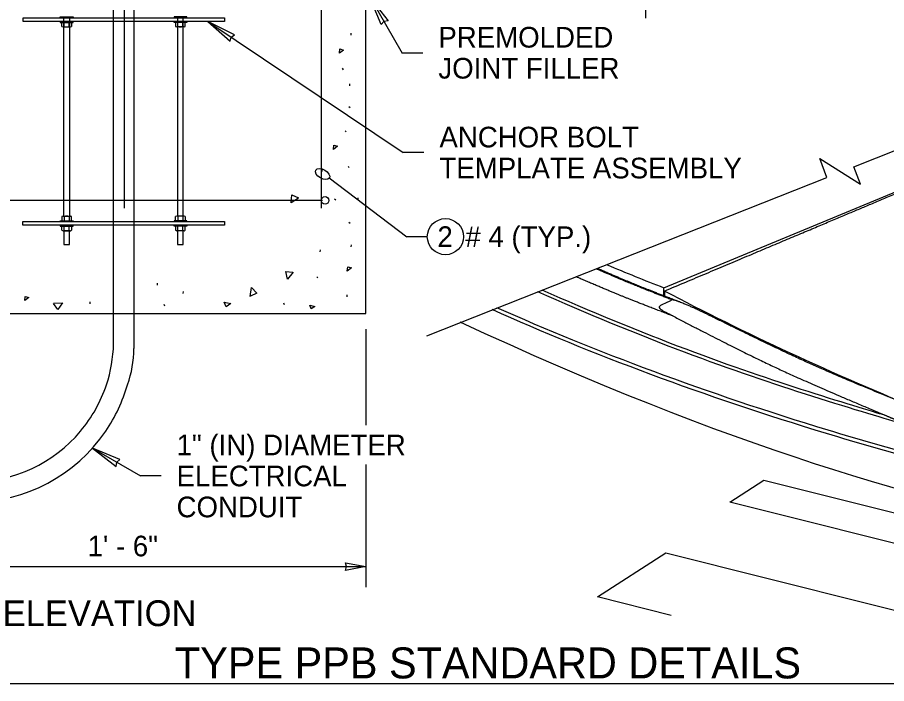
# Model space of a CAD drawing. Extents: x 99862 to 103680, y 99470 to 105076.
# Drawn here: x 101182 to 101855, y 100000 to 100515 of the extents above; entities that cross this region are included whole.
import ezdxf

# ---------------------------------------------------------------- set-up
doc = ezdxf.new("R2010")
doc.units = 0
for name, color, linetype in [('Level 1', 7, 'Continuous'), ('Level 12', 7, 'Continuous'), ('Level 13', 7, 'Continuous'), ('Level 15', 7, 'Continuous'), ('Level 16', 7, 'Continuous'), ('Level 19', 7, 'Continuous'), ('Level 20', 7, 'Continuous'), ('Level 22', 7, 'Continuous'), ('Level 24', 7, 'Continuous'), ('Level 25', 7, 'Continuous'), ('Level 37', 7, 'Continuous'), ('Level 4', 7, 'Continuous')]:
    doc.layers.add(name, color=color, linetype=linetype)

msp = doc.modelspace()

# ---------------------------------------------------------------- linework, layer by layer
at = {"layer": 'Level 1'}
msp.add_lwpolyline([(99862, 99999.5), (103151, 99999.5), (103151, 102075.5), (99862, 102075.5)], close=True, dxfattribs=at)
msp.add_lwpolyline([(101076.55, 100590.62), (101076.55, 100286.04), (101256.16, 100286.04), (101256.2, 100286.04), (101451.55, 100286.04), (101451.55, 100590.62)], dxfattribs=at)
at = {"layer": 'Level 12'}
for p, q in [((101216.1, 100508.44), (101216.1, 100511.61)), ((101217.11, 100508.12), (101222.73, 100508.12)), ((101218, 100508.44), (101218, 100511.61)), ((101221.78, 100508.47), (101221.78, 100511.65)), ((101223.68, 100511.65), (101223.68, 100508.47)), ((101304.19, 100511.65), (101304.19, 100508.47)), ((101310.76, 100508.12), (101305.14, 100508.12)), ((101306.09, 100508.47), (101306.09, 100511.65)), ((101309.88, 100508.44), (101309.88, 100511.61)), ((101311.77, 100508.44), (101311.77, 100511.61)), ((101216.1, 100361.22), (101216.1, 100358.04)), ((101217.11, 100361.54), (101222.73, 100361.54)), ((101218, 100361.22), (101218, 100358.04)), ((101221.78, 100361.18), (101221.78, 100358.01)), ((101223.68, 100358.01), (101223.68, 100361.18)), ((101304.19, 100358.01), (101304.19, 100361.18)), ((101310.76, 100361.54), (101305.14, 100361.54)), ((101306.09, 100361.18), (101306.09, 100358.01)), ((101309.88, 100361.22), (101309.88, 100358.04)), ((101311.77, 100361.22), (101311.77, 100358.04)), ((101216.1, 100350.61), (101216.1, 100353.78)), ((101218, 100350.61), (101218, 100353.78)), ((101221.78, 100350.65), (101221.78, 100353.82)), ((101223.68, 100353.82), (101223.68, 100350.65)), ((101304.19, 100353.82), (101304.19, 100350.65)), ((101306.09, 100350.65), (101306.09, 100353.82)), ((101309.88, 100350.61), (101309.88, 100353.78)), ((101311.77, 100350.61), (101311.77, 100353.78)), ((101217.11, 100350.29), (101222.73, 100350.29)), ((101310.76, 100350.29), (101305.14, 100350.29))]:
    msp.add_line(p, q, dxfattribs=at)
for points in [[(101214.96, 100515.15), (101214.96, 100515.85), (101224.82, 100515.85), (101224.82, 100515.15)], [(101312.91, 100515.15), (101312.91, 100515.85), (101303.05, 100515.85), (101303.05, 100515.15)], [(101214.96, 100512.33), (101214.96, 100511.63), (101224.82, 100511.63), (101224.82, 100512.33)], [(101312.91, 100512.33), (101312.91, 100511.63), (101303.05, 100511.63), (101303.05, 100512.33)], [(101214.96, 100357.32), (101214.96, 100358.03), (101224.82, 100358.03), (101224.82, 100357.32)], [(101214.96, 100354.51), (101214.96, 100353.8), (101224.82, 100353.8), (101224.82, 100354.51)], [(101312.91, 100357.32), (101312.91, 100358.03), (101303.05, 100358.03), (101303.05, 100357.32)], [(101312.91, 100354.51), (101312.91, 100353.8), (101303.05, 100353.8), (101303.05, 100354.51)]]:
    msp.add_lwpolyline(points, dxfattribs=at)
for centre, radius, start, end in [((101217.05, 100509.68), 1.56, 232.65869, 307.34131), ((101219.83, 100514.38), 6.22, 252.81691, 288.29858), ((101222.73, 100509.56), 1.45, 229.05783, 310.95226), ((101305.14, 100509.56), 1.45, 229.04774, 310.94217), ((101308.04, 100514.38), 6.22, 251.70142, 287.18309), ((101310.82, 100509.68), 1.56, 232.65869, 307.34131), ((101217.05, 100359.98), 1.56, 52.65869, 127.34131), ((101219.83, 100355.28), 6.22, 71.70142, 107.18309), ((101222.73, 100360.09), 1.45, 49.04774, 130.94217), ((101305.14, 100360.09), 1.45, 49.05783, 130.95226), ((101308.04, 100355.28), 6.22, 72.81691, 108.29858), ((101310.82, 100359.98), 1.56, 52.65869, 127.34131), ((101217.05, 100351.85), 1.56, 232.65869, 307.34131), ((101219.83, 100356.55), 6.22, 252.81691, 288.29858), ((101222.73, 100351.74), 1.45, 229.05783, 310.95226), ((101305.14, 100351.74), 1.45, 229.04774, 310.94217), ((101308.04, 100356.55), 6.22, 251.70142, 287.18309), ((101310.82, 100351.85), 1.56, 232.65869, 307.34131)]:
    msp.add_arc(centre, radius, start, end, dxfattribs=at)
at = {"layer": 'Level 13'}
for points in [[(101186.06, 100515.15), (101342.23, 100515.15), (101342.23, 100512.33), (101186.06, 100512.33)], [(101186.02, 100357.32), (101342.19, 100357.32), (101342.19, 100354.51), (101186.02, 100354.51)]]:
    msp.add_lwpolyline(points, close=True, dxfattribs=at)
at = {"layer": 'Level 15'}
for p, q in [((101454.82, 100531.18), (101479.84, 100487.84)), ((101329.26, 100512.33), (101480.68, 100410.79)), ((101495.84, 100487.84), (101479.84, 100487.84)), ((101496.68, 100410.79), (101480.68, 100410.79)), ((101423.36, 100391.16), (101483.29, 100345.66)), ((101499.29, 100345.66), (101483.29, 100345.66)), ((101451.55, 100274.04), (101451.55, 100199.73)), ((101239.85, 100181.78), (101277.02, 100160.31)), ((101451.55, 100169.08), (101451.55, 100074.08)), ((101293.02, 100160.31), (101277.02, 100160.31)), ((101076.55, 100090.08), (101451.55, 100090.08))]:
    msp.add_line(p, q, dxfattribs=at)
for points in [[(101668.19, 100603.82), (101668.19, 100567.96), (101675.93, 100567.96), (101660.44, 100552.48), (101668.19, 100552.48), (101668.19, 100514.95)], [(101498.79, 100268.74), (101808.82, 100391.53), (101803.31, 100406.18), (101834.95, 100386.21), (101829.73, 100399.81), (102002.67, 100468.3)]]:
    msp.add_lwpolyline(points, dxfattribs=at)
for points in [[(101454.82, 100531.18), (101468.82, 100512.91), (101465.7, 100512.33), (101463.65, 100509.92)], [(101329.26, 100512.33), (101346.55, 100497.14), (101347.34, 100500.21), (101349.88, 100502.1)], [(101239.85, 100181.78), (101258.12, 100167.78), (101258.7, 100170.89), (101261.11, 100172.95)], [(101451.55, 100090.08), (101435.83, 100086.99), (101436.56, 100090.08), (101435.83, 100093.16)]]:
    msp.add_lwpolyline(points, close=True, dxfattribs=at)
msp.add_ellipse((101418.17, 100394.16), major_axis=(-5.2, 3), ratio=0.57735, dxfattribs=at)
at = {"layer": 'Level 16'}
for p, q in [((101256.2, 100286.04), (101256.2, 100686.74)), ((101271.83, 100686.74), (101271.83, 100286.04)), ((101256.2, 100262.67), (101256.2, 100286.04)), ((101271.83, 100286.04), (101271.83, 100258.98))]:
    msp.add_line(p, q, dxfattribs=at)
for centre, radius, start, end in [((101146.86, 100265.28), 109.38, 341.74861, 358.63542), ((101194.5, 100257.9), 77.33, 339.66254, 0.80445), ((101144.5, 100266.66), 112.05, 320.21568, 341.45254), ((101145.84, 100265.64), 126.02, 325.88535, 344.05402), ((101146.83, 100265.28), 109.38, 270, 319.9948), ((101146.83, 100265.28), 125, 270, 325.77113)]:
    msp.add_arc(centre, radius, start, end, dxfattribs=at)
at = {"layer": 'Level 19'}
for p, q in [((101440.17, 100501.61), (101440.28, 100503.19)), ((101433.37, 100476.06), (101434.02, 100474.76)), ((101439.19, 100462.41), (101439.3, 100463.99)), ((101438.58, 100446.41), (101439.51, 100445.73)), ((101435.57, 100427.72), (101436.5, 100427.04)), ((101437.9, 100400.03), (101438.83, 100399.34)), ((101417.75, 100396.26), (101417.86, 100397.84)), ((101427.49, 100374.93), (101428.42, 100374.25)), ((101445.71, 100374.24), (101445.82, 100375.82)), ((101438.48, 100356.84), (101439.41, 100356.16)), ((101440.4, 100337.77), (101440.51, 100339.34)), ((101416.36, 100333.92), (101416.47, 100335.5)), ((101413.57, 100314.47), (101414.5, 100313.78)), ((101290.13, 100308.15), (101290.24, 100309.73)), ((101310.18, 100301.58), (101310.29, 100303.15)), ((101437.17, 100298.95), (101437.28, 100300.53)), ((101238.03, 100293.67), (101238.13, 100295.24)), ((101295.13, 100293.46), (101295.77, 100292.16)), ((101387.75, 100294.38), (101388.4, 100293.08))]:
    msp.add_line(p, q, dxfattribs=at)
for points in [[(101431.23, 100487.78), (101431.56, 100491.09), (101434.43, 100490.22), (101431.23, 100487.78)], [(101426.51, 100413.28), (101426.83, 100416.59), (101429.71, 100415.72), (101426.51, 100413.28)], [(101399.56, 100375.57), (101393.69, 100371.89), (101394.33, 100378.04), (101399.46, 100375.63)], [(101395.33, 100318.09), (101391.07, 100312.63), (101389.57, 100318.62), (101395.21, 100318.11)], [(101437.26, 100318.98), (101437.58, 100322.29), (101440.45, 100321.42), (101437.26, 100318.98)], [(101362.08, 100299.41), (101363.03, 100306.27), (101367.33, 100301.83), (101362.19, 100299.45)], [(101187.36, 100296.1), (101187.68, 100299.41), (101190.56, 100298.54), (101187.36, 100296.1)], [(101209.65, 100294.1), (101216.57, 100294.35), (101212.94, 100289.35), (101209.71, 100293.99)], [(101347.06, 100293.79), (101343.4, 100291.29), (101341.83, 100294.97), (101347.06, 100293.79)], [(101412.11, 100291.6), (101409.36, 100289.72), (101408.18, 100292.48), (101412.11, 100291.6)]]:
    msp.add_lwpolyline(points, dxfattribs=at)
at = {"layer": 'Level 20'}
msp.add_circle((101513.29, 100345.66), 14, dxfattribs=at)
at = {"layer": 'Level 22'}
for points, degree in [([(101689.01, 100296.63), (101668.98, 100304.43), (101649.42, 100312.42), (101630.35, 100320.6)], 2), ([(101694.6, 100295.11), (101672.88, 100303.48), (101651.73, 100312.09), (101631.15, 100320.91)], 2), ([(101689.42, 100284.27), (101663.77, 100294.05), (101638.86, 100304.14), (101614.71, 100314.52)], 2), ([(101868.07, 100200.48), (101857.33, 100203.6), (101799.88, 100220.68), (101702.21, 100253.55), (101622.16, 100286.24), (101584.94, 100302.94)], 3), ([(101855.05, 100206.92), (101849.13, 100208.67), (101796.66, 100224.43), (101704.32, 100255.51), (101624.94, 100287.87), (101588.32, 100304.26)], 3), ([(101689.01, 100296.63), (101685.29, 100294.97), (101682.01, 100293.23), (101677.75, 100291.36), (101680.63, 100288.84), (101685.03, 100286.64), (101689.01, 100284.47), (101689.42, 100284.27)], 3), ([(101694.69, 100295.08), (101693.13, 100295.65), (101691.58, 100296.29), (101689.75, 100296.64)], 2), ([(101722.57, 100282.35), (101713.61, 100286.74), (101704.55, 100291.12), (101694.69, 100295.08)], 2), ([(102481.65, 100065.04), (102470.71, 100066.1), (102401.87, 100073.06), (102334.07, 100081.62), (102222.02, 100098.24), (102111.99, 100117.08), (101954.64, 100151.69), (101806.49, 100192.34), (101670.46, 100238.13), (101587.98, 100271.84), (101549.47, 100289.15)], 3), ([(102482.21, 100067.76), (102471.26, 100068.82), (102402.47, 100075.77), (102334.73, 100084.32), (102222.8, 100100.92), (102112.91, 100119.74), (101955.73, 100154.32), (101807.75, 100194.92), (101672.73, 100240.37), (101591.05, 100273.69), (101553.24, 100290.62)], 3), ([(102477.39, 100044.55), (102447.94, 100047.42), (102392.79, 100053.37), (102031.32, 100099.54), (101734.5, 100181.6), (101524.73, 100279.53)], 3), ([(101689.42, 100284.27), (101741.59, 100257.15), (101796.94, 100231.29), (101855.05, 100206.92)], 2), ([(101883.13, 100210.83), (101827.07, 100233.36), (101773.42, 100257.25), (101722.57, 100282.35)], 2), ([(101855.05, 100206.92), (101859.51, 100204.98), (101864.21, 100203.1), (101867.89, 100200.83)], 2)]:
    msp.add_open_spline(points, degree=degree, dxfattribs=at)
at = {"layer": 'Level 24'}
for points in [[(102099.46, 100072.14), (102073.01, 100055.09), (101733.55, 100140.13), (101760, 100157.18), (102099.46, 100072.14)], [(101688.2, 100052.35), (101631.04, 100066.67), (101683.94, 100100.78), (101920.99, 100041.39)]]:
    msp.add_lwpolyline(points, dxfattribs=at)
at = {"layer": 'Level 25'}
for p, q in [((101264.66, 100367.65), (101264.66, 100673.98)), ((101417.32, 100367.65), (101417.32, 100673.98)), ((101418.12, 100373.76), (101111.21, 100373.76))]:
    msp.add_line(p, q, dxfattribs=at)
msp.add_circle((101420.06, 100373.76), 2.92, dxfattribs=at)
at = {"layer": 'Level 37'}
for p, q in [((101682.46, 100306.12), (101987.6, 100432.32)), ((101682.59, 100299.79), (101682.46, 100306.12))]:
    msp.add_line(p, q, dxfattribs=at)
msp.add_ellipse((102913.55, 100826.46), major_axis=(1749.62, 27.04), ratio=0.40566, start_param=3.889727, end_param=3.925643, dxfattribs=at)
for points, degree in [([(101683.03, 100303.55), (101784.55, 100346.33), (101886.08, 100389.11), (101987.61, 100431.88)], 2), ([(101886.89, 100209.32), (101849.5, 100224.46), (101779.29, 100254.9), (101713.61, 100287.41), (101683.03, 100303.55)], 3), ([(101683.03, 100303.55), (101683.06, 100302.23), (101683.08, 100300.91), (101683.11, 100299.58)], 2)]:
    msp.add_open_spline(points, degree=degree, dxfattribs=at)
at = {"layer": 'Level 4'}
for p, q in [((101217.78, 100361.54), (101217.78, 100515.15)), ((101222.05, 100515.15), (101222.05, 100361.54)), ((101305.79, 100515.15), (101305.79, 100361.54)), ((101310.05, 100361.54), (101310.05, 100515.15))]:
    msp.add_line(p, q, dxfattribs=at)
for points in [[(101217.78, 100350.29), (101217.78, 100339.71), (101222.05, 100339.71), (101222.05, 100350.29)], [(101305.79, 100350.29), (101305.79, 100339.71), (101310.05, 100339.71), (101310.05, 100350.29)]]:
    msp.add_lwpolyline(points, dxfattribs=at)

# ---------------------------------------------------------------- texts
at = {"layer": 'Level 20'}
for s, height, p in [('PREMOLDED ', 16, (101507.84, 100492.11)), ('JOINT FILLER', 16, (101507.84, 100468.11)), ('ANCHOR BOLT', 16, (101508.68, 100414.79)), ('TEMPLATE ASSEMBLY', 16, (101508.68, 100390.79)), ('2', 16, (101507.11, 100337.66)), ('    # 4 (TYP.)', 16, (101504.98, 100337.57)), ('1\' - 6"', 16, (101236.12, 100098.08)), ('ELEVATION', 20, (101170.29, 100044.01)), ('TYPE PPB STANDARD DETAILS', 24, (101303.71, 100003.53))]:
    msp.add_text(s, height=height, dxfattribs=at).set_placement(p)
for s, p in [('1" (IN) DIAMETER', (101305.02, 100176.32)), ('ELECTRICAL', (101305.02, 100152.32)), ('CONDUIT', (101305.02, 100128.32))]:
    msp.add_text(s, height=16, rotation=360, dxfattribs=at).set_placement(p)

doc.saveas('drawing.dxf')
